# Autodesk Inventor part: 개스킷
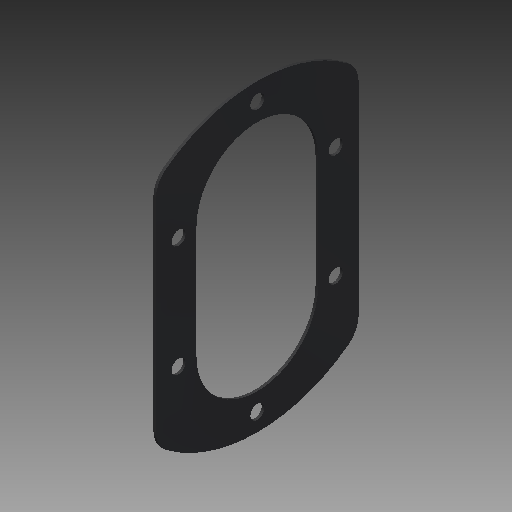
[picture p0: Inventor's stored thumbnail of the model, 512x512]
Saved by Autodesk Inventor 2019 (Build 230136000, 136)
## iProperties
Created: 2019-03
Part Number: 개스킷
Material: 고무
Document SubType Name: Modeling
Designer: mduedu
Density: 1 g/cm^3
Appearance: 고무 - 검은색 - 버전 1.1
Author: mduedu
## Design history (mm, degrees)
sketch "스케치1"
  geometry: L1 (-44.721, -40)-(44.721, -40); L2 (44.721, 40)-(-44.721, 40); A1 r 60 centre (0, 0) between (44.721, -40) and (44.721, 40); A2 r 60 centre (0, 0) between (-44.721, 40) and (-44.721, -40); 5 further points
  constraints: 6 point on circle, 4 end point, 2 centre point, 2 coincident, 2 horizontal alignment, 2 midpoint, 2 vertical alignment, 1 horizontal, 1 parallel
  dimensions: "d0" = 60 radius of A1; "d2" = 80 distance between parallel lines of L2 L1
extrude "돌출1" new body sketch "스케치1" distance "d3" = 1; taper "d4" = 0 deg
fillet "모깎기1" dims "d5" = 10
sketch "스케치2" dims "d6" = 48
  geometry: L1 (-24, -22)-(24, -22); L2 (24, -22)-(24, 22); L3 (24, 22)-(-24, 22); L4 (-24, 22)-(-24, -22); L5 (-24, -22)-(24, 22); L6 (24, -22)-(-24, 22); 3 further points
  constraints: 12 end point, 4 midpoint, 2 horizontal alignment, 2 parallel, 1 horizontal, 1 perpendicular, 4 other
  dimensions: "d8" = 22 distance from line of L3 point (0, 0)
extrude "돌출2" cut sketch "스케치2" extent not by distance; stored distance "d9" = 1; taper "d10" = 0 deg
sketch "스케치3" dims "d0" = 60, "d2" = 80
  geometry: L1 (31, -22)-(31, 22); L2 (-31, 22)-(-31, -22); L3 (-31, -22)-(31, 22); L4 (31, -22)-(-31, 22); A1 r 31 centre (0, 22) between (31, 22) and (-31, 22); A2 r 31 centre (0, -22) between (-31, -22) and (31, -22); 8 further points
  constraints: 8 end point, 6 point on circle, 4 coincident, 4 midpoint, 3 tangent, 2 centre point, 2 vertical alignment, 1 parallel
  dimensions: "d11" = 31 radius of A1; "d13" = 44 distance of A2.centre A1.centre
hole "구멍1" sketch "스케치3" at (-31, 22), (-31, -22), (31, -22), (31, 22), (0, -53), (0, 53) diameter "d14" = 5.5; stored, may be unused: countersink angle "d18" = 90 deg, drill point angle "d20" = 118 deg; dims "d15" = 6, "d16" = 4, "d17" = 2, "d19" = 8
node "솔리드1"
